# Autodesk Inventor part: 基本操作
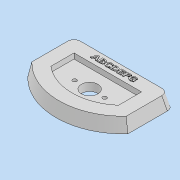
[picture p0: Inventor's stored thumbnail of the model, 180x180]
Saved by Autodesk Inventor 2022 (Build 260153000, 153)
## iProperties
Created: 2019-12
Part Number: 基本操作
Material: 一般
Document SubType Name: Modeling
Designer: 吉田
Density: 1 g/cm^3
Appearance: 既定
Author: 吉田
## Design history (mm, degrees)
sketch "スケッチ1"
  geometry: L1 (-75, 0)-(75, 0); L2 (75, 0)-(75, -69.13); L3 (75, -69.13)-(-75, -69.13); L4 (-75, -69.13)-(-75, 0); A1 r 102 centre (0, 0) between (-75, -69.13) and (75, -69.13); 2 further points
  constraints: 8 end point, 2 coincident, 2 parallel, 2 point on circle, 1 centre point, 1 horizontal, 1 midpoint, 1 perpendicular
  dimensions: "d0" = 150 distance of L2.end L3.end; "d23" = 102 radius of A1
extrude "押し出し1" new body sketch "スケッチ1" distance "d2" = 20; taper "d3" = 0 deg
feature "面の勾配1" dims angle "d4" = 12 deg
sketch "スケッチ2"
  geometry: L1 (70.749, -67.45)-(70.749, -4.251) reference; L2 (70.749, -4.251)-(-70.749, -4.251) reference; L3 (-70.749, -4.251)-(-70.749, -67.45) reference; L4 (-50.749, -24.251)-(50.749, -24.251); L5 (50.749, -24.251)-(50.749, -58.902); L6 (-50.749, -58.902)-(-50.749, -24.251); A1 r 77.749 centre (0, 0) between (-50.749, -58.902) and (50.749, -58.902); A2 r 97.749 centre (0, 0) between (-70.749, -67.45) and (70.749, -67.45) reference; A3 r 97.749 centre (0, 0) between (-70.749, -67.45) and (70.749, -67.45) reference; 3 further points
  constraints: 6 end point, 3 point on circle, 2 vertical alignment, 1 centre point, 1 concentric, 1 midpoint, 1 other
  dimensions: "d5" = 20 distance between parallel lines of L2 L4; "d27" = 20 radial gap between concentric circles of A2 A1
extrude "押し出し2" cut sketch "スケッチ2" distance "d6" = 8; taper "d7" = 0 deg
fillet "フィレット1" dims "d8" = 10
sketch "スケッチ3"
  geometry: L1 (65.219, 0)-(-65.219, 0) reference; L2 (-50.749, -24.251)-(50.749, -24.251) reference; L3 (0, -24.251)-(0, -77.749); C1 r 12.5 at (0, -51.5); A1 r 77.749 centre (0, 0) between (-50.749, -58.902) and (50.749, -58.902) reference; 2 further points
  constraints: 2 end point, 2 midpoint, 1 centre point, 1 point on circle, 1 vertical, 1 vertical alignment
  dimensions: "d9" = 25 diameter of C1; "d24" = 51.5 distance from line of L1 C1.centre
extrude "押し出し3" cut sketch "スケッチ3" extent not by distance; stored distance "d11" = 8; taper "d12" = 0 deg
sketch "スケッチ4"
  geometry: L1 (-22.5, -51.5)-(22.5, -51.5); 7 further points
  constraints: 3 coincident, 2 end point, 1 horizontal, 1 midpoint, 1 other
  dimensions: "d13" = 45 distance of L1.start L1.end
hole "穴1" sketch "スケッチ4" at (-22.5, -51.5), (22.5, -51.5) diameter "d14" = 6; stored, may be unused: countersink angle "d18" = 90 deg, drill point angle "d20" = 118 deg; dims "d15" = 6, "d16" = 4, "d17" = 2, "d19" = 4
sketch "スケッチ5"
  geometry: L1 (-50.749, -10.251)-(50.749, -10.251); L2 (50.749, -10.251)-(50.749, -18.251); L3 (50.749, -18.251)-(-50.749, -18.251); L4 (-50.749, -18.251)-(-50.749, -10.251); L5 (60.967, -4.251)-(-60.967, -4.251) reference; 3 further points
  constraints: 2 vertical alignment, 2 other
  dimensions: "d25" = 6 distance between parallel lines of L5 L1; "d26" = 8 distance between parallel lines of L3 L1
feature "エンボス1" sketch "スケッチ5" dims "d21" = 1, "d22" = 0
node "ソリッド1"
node "投影ループ1"
